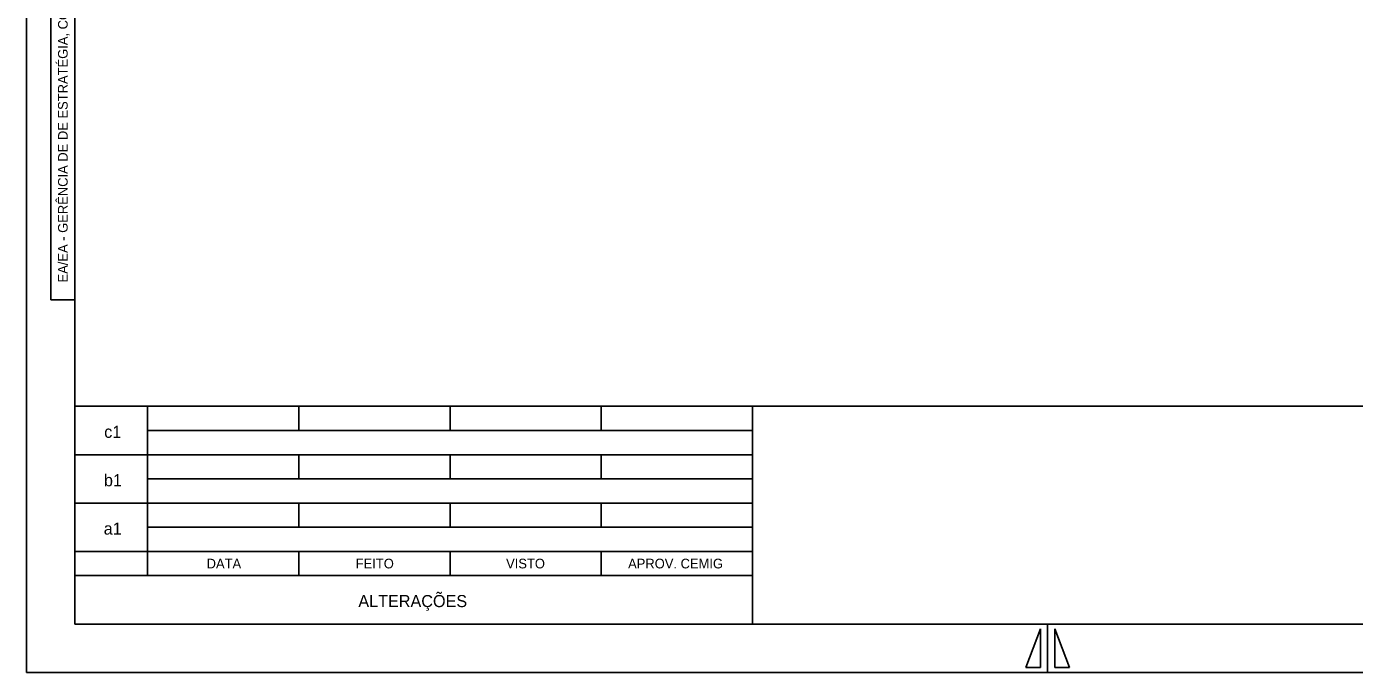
# Model space of a CAD drawing. Extents: x 563 to 1404, y 358 to 952.
# Drawn here: x 562.6 to 837, y 358 to 491.5 of the extents above; entities that cross this region are included whole.
import ezdxf

# ---------------------------------------------------------------- set-up
doc = ezdxf.new("R2010")
doc.units = 0
doc.layers.add('New Level (0)', color=7, linetype='Continuous')

msp = doc.modelspace()

# ---------------------------------------------------------------- linework, layer by layer
at = {"layer": 'New Level (0)'}
for p, q in [((562.58, 951.96), (562.58, 357.96)), ((562.58, 951.96), (562.58, 357.96)), ((572.58, 941.96), (572.58, 367.96)), ((572.58, 941.96), (572.58, 367.96)), ((567.58, 434.97), (567.58, 638.29)), ((572.58, 434.97), (567.58, 434.97)), ((572.58, 412.96), (1393.58, 412.96)), ((587.58, 377.96), (587.58, 412.96)), ((618.83, 407.96), (618.83, 412.96)), ((650.08, 407.96), (650.08, 412.96)), ((681.33, 407.96), (681.33, 412.96)), ((712.58, 412.96), (712.58, 367.96)), ((587.58, 407.96), (712.58, 407.96)), ((572.58, 402.96), (712.58, 402.96)), ((618.83, 397.96), (618.83, 402.96)), ((650.08, 397.96), (650.08, 402.96)), ((681.33, 397.96), (681.33, 402.96)), ((587.58, 397.96), (712.58, 397.96)), ((572.58, 392.96), (712.58, 392.96)), ((618.83, 387.96), (618.83, 392.96)), ((650.08, 387.96), (650.08, 392.96)), ((681.33, 387.96), (681.33, 392.96)), ((587.58, 387.96), (712.58, 387.96)), ((572.58, 382.96), (712.58, 382.96)), ((618.83, 377.96), (618.83, 382.96)), ((650.08, 377.96), (650.08, 382.96)), ((681.33, 377.96), (681.33, 382.96)), ((572.58, 377.96), (712.58, 377.96)), ((572.58, 367.96), (1393.58, 367.96)), ((572.58, 367.96), (1393.58, 367.96)), ((773.58, 367.96), (773.58, 357.96)), ((769.08, 358.96), (772.08, 366.96)), ((772.08, 366.96), (772.08, 358.96)), ((775.08, 366.96), (775.08, 358.96)), ((778.08, 358.96), (775.08, 366.96)), ((562.58, 357.96), (1403.58, 357.96)), ((562.58, 357.96), (1403.58, 357.96)), ((772.08, 358.96), (769.08, 358.96)), ((775.08, 358.96), (778.08, 358.96))]:
    msp.add_line(p, q, dxfattribs=at)

# ---------------------------------------------------------------- texts
msp.add_text('EA/EA - GERÊNCIA DE DE ESTRATÉGIA, CONTROLE, ESTUDOS E PROJETOS DA EXPANSÃO E MANUTENÇÃO DA  ALTA TENSÃO DA DISTRIBUIÇÃO', height=2, rotation=90, dxfattribs=at).set_placement((571.08, 438.56))
for s, height, p in [('c1', 2.5, (578.62, 406.44)), ('b1', 2.5, (578.57, 396.44)), ('a1', 2.5, (578.52, 386.44)), ('DATA', 2, (599.79, 379.46)), ('FEITO', 2, (630.6, 379.46)), ('VISTO', 2, (661.67, 379.46)), ('APROV. CEMIG', 2, (686.88, 379.46)), ('ALTERAÇÕES', 2.5, (631.14, 371.46))]:
    msp.add_text(s, height=height, dxfattribs=at).set_placement(p)

doc.saveas('drawing.dxf')
